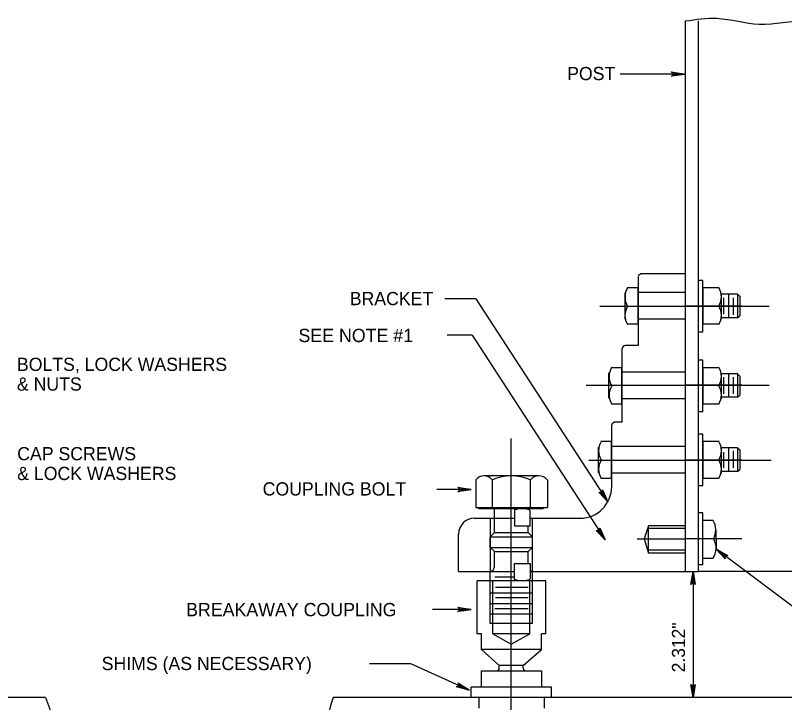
# Model space of a CAD drawing. Extents: x 637580 to 641008, y 294594 to 295782.
# Drawn here: x 637787.5 to 637964.6, y 294775.2 to 294933.4 of the extents above; entities that cross this region are included whole.
import ezdxf

# ---------------------------------------------------------------- set-up
doc = ezdxf.new("R2010")
doc.units = 0
for name, color, linetype in [('1', 7, 'Continuous'), ('2', 7, 'Continuous'), ('3', 7, 'Continuous')]:
    doc.layers.add(name, color=color, linetype=linetype)

# ---------------------------------------------------------------- blocks, each defined once
blk = doc.blocks.new('RARROW')
at = {"layer": '3'}
blk.add_lwpolyline([(-2.2695, 0.285), (-2.184875, 0.12075), (0, 0), (-2.2695, 0.285), (-2.38575, 0.384625), (0, 0), (-2.183125, -0.108), (-2.262875, -0.2705), (0, 0), (-2.38575, -0.379125), (-2.262875, -0.2705)], dxfattribs=at)

msp = doc.modelspace()

# ---------------------------------------------------------------- linework, layer by layer
at = {"layer": '2'}
for p, q in [((637941.8, 294866.5), (637941.8, 294932.13)), ((637944.8, 294805.38), (637944.8, 294932.13)), ((637941.55, 294919.88), (637926.8, 294919.88)), ((637941.8, 294873.88), (637931.43, 294873.88)), ((637930.93, 294873.13), (637930.93, 294857.38)), ((637945.8, 294872.38), (637944.93, 294872.38)), ((637945.8, 294860.5), (637945.8, 294872.38)), ((637928.43, 294870.75), (637930.93, 294870.75)), ((637930.93, 294862.38), (637930.93, 294870.75)), ((637930.93, 294862.38), (637930.93, 294870.75)), ((637945.8, 294870.75), (637945.8, 294862.38)), ((637945.8, 294870.75), (637949.55, 294870.75)), ((637927.93, 294866.5), (637927.93, 294869.5)), ((637941.8, 294869.63), (637930.93, 294869.63)), ((637950.05, 294869.25), (637950.05, 294866.5)), ((637953.8, 294869.25), (637950.05, 294869.25)), ((637950.55, 294868.38), (637950.55, 294864.63)), ((637951.68, 294869.25), (637951.68, 294863.75)), ((637952.8, 294868.38), (637952.8, 294864.5)), ((637953.8, 294869.25), (637953.8, 294863.75)), ((637953.8, 294869.25), (637954.3, 294868.75)), ((637954.3, 294868.75), (637954.3, 294864.25)), ((637893.55, 294868.13), (637886.39, 294868.13)), ((637893.55, 294868.13), (637923.93, 294821.38)), ((637922.05, 294866.5), (637961.05, 294866.5)), ((637927.93, 294866.5), (637930.93, 294866.5)), ((637927.93, 294866.5), (637927.93, 294866.5)), ((637927.93, 294863.5), (637927.93, 294866.5)), ((637930.93, 294866.5), (637930.93, 294866.5)), ((637930.93, 294866.5), (637930.93, 294866.5)), ((637930.93, 294866.5), (637930.93, 294866.5)), ((637930.93, 294866.5), (637930.93, 294866.5)), ((637930.93, 294866.5), (637930.93, 294866.5)), ((637941.8, 294848.25), (637941.8, 294866.5)), ((637954.8, 294866.5), (637941.8, 294866.5)), ((637945.8, 294866.5), (637945.8, 294866.5)), ((637945.8, 294866.5), (637950.05, 294866.5)), ((637945.8, 294866.5), (637945.8, 294866.5)), ((637950.05, 294866.5), (637950.05, 294866.5)), ((637950.05, 294866.5), (637950.05, 294863.5)), ((637950.05, 294866.5), (637950.05, 294866.5)), ((637941.8, 294863.5), (637930.93, 294863.5)), ((637953.8, 294863.75), (637950.05, 294863.75)), ((637953.8, 294863.75), (637954.3, 294864.25)), ((637928.43, 294862.38), (637930.93, 294862.38)), ((637945.8, 294862.38), (637949.43, 294862.38)), ((637892.68, 294859.75), (637886.95, 294859.75)), ((637892.68, 294859.75), (637923.3, 294812.63)), ((637945.8, 294860.5), (637944.68, 294860.5)), ((637927.18, 294856.75), (637927.18, 294839.75)), ((637930.93, 294857.38), (637927.93, 294857.38)), ((637924.8, 294852.38), (637927.18, 294852.38)), ((637927.18, 294844), (637927.18, 294852.38)), ((637927.18, 294844), (637927.18, 294852.38)), ((637927.18, 294844), (637927.18, 294852.38)), ((637945.8, 294854), (637944.93, 294854)), ((637945.8, 294842.13), (637945.8, 294854)), ((637945.8, 294852.38), (637945.8, 294844)), ((637945.8, 294852.38), (637949.55, 294852.38)), ((637924.18, 294848.25), (637924.18, 294851.13)), ((637941.8, 294851.25), (637927.18, 294851.25)), ((637950.05, 294851), (637950.05, 294848.25)), ((637953.8, 294850.88), (637950.05, 294850.88)), ((637951.68, 294850.88), (637951.68, 294845.5)), ((637953.8, 294850.88), (637953.8, 294845.5)), ((637953.8, 294850.88), (637954.3, 294850.38)), ((637950.55, 294850.13), (637950.55, 294846.25)), ((637952.8, 294850.13), (637952.8, 294846.25)), ((637954.3, 294850.38), (637954.3, 294846)), ((637918.93, 294848.25), (637961.05, 294848.25)), ((637924.18, 294848.25), (637927.18, 294848.25)), ((637924.18, 294848.25), (637924.18, 294848.25)), ((637924.18, 294845.25), (637924.18, 294848.13)), ((637927.18, 294848.25), (637927.18, 294848.25)), ((637927.18, 294848.25), (637927.18, 294848.25)), ((637927.18, 294848.25), (637927.18, 294848.25)), ((637927.18, 294848.25), (637927.18, 294848.25)), ((637927.18, 294848.25), (637927.18, 294848.25)), ((637927.18, 294848.25), (637927.18, 294848.25)), ((637927.18, 294848.25), (637927.18, 294848.25)), ((637927.18, 294848.25), (637927.18, 294848.25)), ((637941.8, 294831), (637941.8, 294848.25)), ((637954.8, 294848.25), (637941.8, 294848.25)), ((637945.8, 294848.25), (637945.8, 294848.25)), ((637945.8, 294848.25), (637945.8, 294848.25)), ((637945.8, 294848.25), (637950.05, 294848.25)), ((637945.8, 294848.25), (637945.8, 294848.25)), ((637950.05, 294848.25), (637950.05, 294848.25)), ((637950.05, 294848.25), (637950.05, 294845.13)), ((637950.05, 294848.25), (637950.05, 294848.25)), ((637953.8, 294845.5), (637950.05, 294845.5)), ((637953.8, 294845.5), (637954.3, 294846)), ((637924.8, 294844), (637927.18, 294844)), ((637941.8, 294845.13), (637927.18, 294845.13)), ((637945.8, 294844), (637949.43, 294844)), ((637945.8, 294842.13), (637944.8, 294842.13)), ((637924.8, 294839.13), (637924.8, 294825)), ((637927.18, 294839.75), (637925.3, 294839.75)), ((637945.8, 294837), (637944.93, 294837)), ((637945.8, 294825.13), (637945.8, 294837)), ((637901.68, 294768.25), (637901.68, 294836)), ((637922.3, 294835.38), (637924.8, 294835.38)), ((637924.8, 294826.88), (637924.8, 294835.38)), ((637924.8, 294826.88), (637924.8, 294835.38)), ((637924.8, 294826.88), (637924.8, 294835.38)), ((637924.8, 294826.88), (637924.8, 294835.38)), ((637945.8, 294835.38), (637945.8, 294826.88)), ((637945.8, 294835.38), (637949.55, 294835.38)), ((637921.8, 294831.13), (637921.8, 294834)), ((637941.8, 294834.13), (637924.8, 294834.13)), ((637950.05, 294833.88), (637950.05, 294831.13)), ((637953.8, 294833.88), (637950.05, 294833.88)), ((637950.55, 294832.88), (637950.55, 294829.25)), ((637951.68, 294833.88), (637951.68, 294828.38)), ((637952.8, 294833.13), (637952.8, 294829.25)), ((637953.8, 294833.88), (637953.8, 294828.38)), ((637953.8, 294833.88), (637954.3, 294833.38)), ((637954.3, 294833.38), (637954.3, 294828.88)), ((637950.05, 294831.13), (637950.05, 294828)), ((637919.55, 294831), (637961.55, 294831)), ((637921.8, 294831), (637924.8, 294831)), ((637921.8, 294831), (637921.8, 294831)), ((637921.8, 294828.13), (637921.8, 294831)), ((637924.8, 294831), (637924.8, 294831)), ((637924.8, 294831), (637924.8, 294831)), ((637924.8, 294831), (637924.8, 294831)), ((637924.8, 294831), (637924.8, 294831)), ((637924.8, 294831), (637924.8, 294831)), ((637924.8, 294831), (637924.8, 294831)), ((637924.8, 294831), (637924.8, 294831)), ((637924.8, 294831), (637924.8, 294831)), ((637924.8, 294831), (637924.8, 294831)), ((637924.8, 294831), (637924.8, 294831)), ((637941.8, 294812.88), (637941.8, 294831)), ((637954.8, 294831), (637941.8, 294831)), ((637945.8, 294831), (637945.8, 294831)), ((637945.8, 294831), (637945.8, 294831)), ((637945.8, 294831), (637945.8, 294831)), ((637945.8, 294831), (637950.05, 294831)), ((637945.8, 294831), (637945.8, 294831)), ((637950.05, 294831), (637950.05, 294831)), ((637950.05, 294831), (637950.05, 294831)), ((637941.8, 294828), (637924.8, 294828)), ((637953.8, 294828.38), (637950.05, 294828.38)), ((637953.8, 294828.38), (637954.3, 294828.88)), ((637893.55, 294826.5), (637893.55, 294826.5)), ((637893.55, 294826.5), (637893.55, 294820.13)), ((637895.43, 294827.5), (637895.43, 294827.5)), ((637895.43, 294827.5), (637897.3, 294827.5)), ((637897.3, 294827.5), (637906.05, 294827.5)), ((637897.3, 294826.5), (637897.3, 294820.13)), ((637897.3, 294826.5), (637897.3, 294826.5)), ((637901.68, 294827.5), (637901.68, 294827.5)), ((637901.68, 294793.88), (637901.68, 294827.38)), ((637906.05, 294827.5), (637907.93, 294827.5)), ((637906.05, 294826.5), (637906.05, 294820.25)), ((637906.05, 294826.5), (637906.05, 294826.5)), ((637907.93, 294827.5), (637907.93, 294827.5)), ((637910.05, 294826.5), (637910.05, 294826.5)), ((637910.05, 294826.5), (637910.05, 294820.13)), ((637922.3, 294826.88), (637924.8, 294826.88)), ((637945.8, 294826.88), (637949.43, 294826.88)), ((637892.42, 294824.25), (637884.57, 294824.25)), ((637945.8, 294825.13), (637944.8, 294825.13)), ((637893.55, 294820.13), (637910.05, 294820.13)), ((637894.18, 294819.88), (637894.05, 294820.13)), ((637894.18, 294819.88), (637909.05, 294819.88)), ((637897.8, 294814.38), (637897.8, 294820.13)), ((637901.68, 294819.88), (637901.68, 294819.88)), ((637901.68, 294819.88), (637901.68, 294819.88)), ((637902.43, 294819.5), (637902.43, 294815.88)), ((637904.18, 294819.88), (637904.18, 294819.88)), ((637906.05, 294815.88), (637906.05, 294819.5)), ((637909.05, 294819.88), (637909.18, 294820.25)), ((637945.8, 294818.88), (637944.8, 294818.88)), ((637945.8, 294806.88), (637945.8, 294818.88)), ((637893.18, 294817.63), (637902.3, 294817.63)), ((637896.8, 294817.63), (637896.8, 294805.38)), ((637906.05, 294817.63), (637917.55, 294817.63)), ((637906.55, 294805.38), (637906.55, 294817.63)), ((637945.8, 294808.38), (637945.8, 294817.13)), ((637945.8, 294808.38), (637945.8, 294817.13)), ((637948.18, 294817.13), (637945.8, 294817.13)), ((637902.43, 294815.88), (637906.05, 294815.88)), ((637904.18, 294815.88), (637904.18, 294815.88)), ((637905.55, 294814.38), (637905.55, 294815.88)), ((637933.3, 294815.88), (637932.3, 294812.88)), ((637941.8, 294815.88), (637933.3, 294815.88)), ((637933.3, 294809.63), (637933.3, 294815.88)), ((637941.8, 294815.25), (637933.3, 294815.25)), ((637889.55, 294805.38), (637889.55, 294814)), ((637896.8, 294813.38), (637897.8, 294814.38)), ((637896.8, 294813.38), (637906.55, 294813.38)), ((637896.8, 294810.88), (637896.8, 294813.38)), ((637897.8, 294814.38), (637905.55, 294814.38)), ((637906.55, 294813.38), (637905.55, 294814.38)), ((637906.55, 294810.88), (637906.55, 294813.38)), ((637948.78, 294814.93), (637948.88, 294810.69)), ((637930.68, 294812.88), (637941.8, 294812.88)), ((637932.3, 294812.88), (637933.3, 294809.63)), ((637941.8, 294805.38), (637941.8, 294812.88)), ((637954.8, 294812.88), (637941.8, 294812.88)), ((637945.8, 294812.88), (637945.8, 294812.88)), ((637945.8, 294812.88), (637945.8, 294812.88)), ((637945.8, 294812.88), (637945.8, 294812.88)), ((637945.8, 294812.88), (637945.8, 294812.88)), ((637945.8, 294812.88), (637945.8, 294812.88)), ((637948.93, 294812.88), (637945.8, 294812.88)), ((637945.8, 294812.88), (637945.8, 294812.88)), ((637896.8, 294810.88), (637906.55, 294810.88)), ((637897.8, 294810), (637896.8, 294810.88)), ((637897.8, 294806.38), (637897.8, 294810)), ((637897.8, 294810), (637905.55, 294810)), ((637901.68, 294810.63), (637901.68, 294810.63)), ((637901.68, 294810.63), (637901.68, 294810.63)), ((637905.55, 294810), (637906.55, 294810.88)), ((637905.55, 294807.25), (637905.55, 294810)), ((637941.8, 294810.25), (637933.3, 294810.25)), ((637969.48, 294795.04), (637948.86, 294810.49)), ((637941.8, 294809.63), (637933.3, 294809.63)), ((637948.09, 294808.38), (637945.8, 294808.38)), ((637902.43, 294807.25), (637906.05, 294807.25)), ((637902.43, 294803.63), (637902.43, 294807.25)), ((637904.18, 294807.25), (637904.18, 294807.25)), ((637906.05, 294807.25), (637906.05, 294803.63)), ((637945.8, 294806.88), (637944.93, 294806.88)), ((637889.55, 294805.38), (637889.55, 294805.38)), ((637889.55, 294805.38), (637902.43, 294805.38)), ((637896.8, 294795.63), (637896.8, 294805.38)), ((637901.68, 294805.38), (637901.68, 294805.38)), ((637901.68, 294805.38), (637901.68, 294805.38)), ((637906.05, 294805.38), (637944.8, 294805.38)), ((637906.55, 294795.63), (637906.55, 294805.38)), ((637943.55, 294805.38), (637943.55, 294776.38)), ((638075.05, 294805.38), (637944.8, 294805.38)), ((637893.8, 294791), (637893.8, 294803.25)), ((637909.68, 294803.25), (637893.8, 294803.25)), ((637896.8, 294793.38), (637896.8, 294803.25)), ((637897.43, 294791), (637897.43, 294803.25)), ((637897.93, 294804.13), (637902.3, 294804.13)), ((637901.68, 294803.25), (637901.68, 294803.25)), ((637901.68, 294803.25), (637901.68, 294803.25)), ((637904.18, 294803.25), (637904.18, 294803.25)), ((637905.93, 294791), (637905.93, 294803.25)), ((637906.55, 294793.38), (637906.55, 294803.25)), ((637909.68, 294791), (637909.68, 294803.25)), ((637898.05, 294801.75), (637905.55, 294801.75)), ((637896.8, 294800.5), (637906.55, 294800.5)), ((637898.05, 294799.38), (637905.55, 294799.38)), ((637896.8, 294798), (637906.55, 294798)), ((637892.42, 294796.63), (637883.56, 294796.63)), ((637897.93, 294796.88), (637905.55, 294796.88)), ((637896.8, 294795.63), (637906.55, 294795.63)), ((637901.68, 294795.63), (637901.68, 294795.63)), ((637906.55, 294793.38), (637896.8, 294793.38)), ((637894.8, 294791), (637893.8, 294791)), ((637894.8, 294787.38), (637894.8, 294791)), ((637905.93, 294791), (637897.43, 294791)), ((637897.43, 294791), (637901.68, 294788.63)), ((637901.68, 294788.63), (637905.93, 294791)), ((637908.68, 294787.38), (637908.68, 294791)), ((637909.68, 294791), (637908.68, 294791)), ((637901.68, 294788.63), (637901.68, 294788.63)), ((637898.93, 294783.75), (637894.8, 294787.38)), ((637908.68, 294787.38), (637894.8, 294787.38)), ((637904.43, 294783.75), (637908.68, 294787.38)), ((637878.55, 294784.13), (637869.06, 294784.13)), ((637892, 294778.06), (637878.55, 294784.13)), ((637904.43, 294783.75), (637898.93, 294783.75)), ((637898.93, 294783.1), (637898.93, 294783.75)), ((637904.43, 294783.1), (637904.43, 294783.75)), ((637894.8, 294782.5), (637908.68, 294782.5)), ((637894.8, 294778.75), (637894.8, 294782.5)), ((637908.68, 294782.5), (637908.68, 294778.75)), ((637910.93, 294778.75), (637892.43, 294778.75)), ((637892.43, 294776.38), (637892.43, 294778.75)), ((637901.68, 294778.75), (637901.68, 294778.75)), ((637910.93, 294776.38), (637910.93, 294778.75)), ((637794.44, 294776.38), (637673.31, 294776.38)), ((638166.68, 294776.38), (637860.68, 294776.38)), ((637910.93, 294776.38), (637892.43, 294776.38)), ((637894.18, 294776.38), (637894.18, 294773.88)), ((637909.3, 294773.88), (637909.3, 294776.38))]:
    msp.add_line(p, q, dxfattribs=at)
for centre, start, end in [((637898.33, 294783.1), 270, 0), ((637905.03, 294783.1), 180, 270)]:
    msp.add_arc(centre, 0.6, start, end, dxfattribs=at)
for centre, major_axis, start_param, end_param in [((637931.52, 294873.21), (0, -0.61), 3.141593, 4.712389), ((637932.04, 294868.59), (0, -4.18), 4.16723, 5.257548), ((637946.02, 294868.62), (0, 4.08), 4.160577, 5.264201), ((637931.77, 294864.33), (0, -3.91), 4.129616, 5.27673), ((637946.14, 294864.34), (0, 3.96), 4.15179, 5.282205), ((637927.86, 294856.74), (0, -0.61), 3.141593, 4.712389), ((637928.38, 294850.26), (0, -4.18), 4.16723, 5.257548), ((637946.02, 294850.29), (0, 4.08), 4.160577, 5.264201), ((637928.11, 294846), (0, -3.91), 4.129616, 5.27673), ((637946.14, 294846.02), (0, 3.96), 4.15179, 5.282205), ((637925.43, 294839.04), (0, -0.61), 3.141593, 4.712389), ((637925.95, 294833.17), (0, -4.18), 4.16723, 5.257548), ((637946.02, 294833.2), (0, 4.08), 4.160577, 5.264201), ((637925.68, 294828.91), (0, -3.91), 4.129616, 5.27673), ((637946.14, 294828.92), (0, 3.96), 4.15179, 5.282205), ((637901.69, 294816.68), (0, -10.74), 2.718335, 3.56485), ((637895.4, 294825.03), (0, -2.39), 2.218404, 4.064781), ((637908.01, 294824.98), (0, -2.44), 2.228521, 4.054665), ((637917.52, 294824.96), (0, -7.33), 0, 1.570796), ((637904.16, 294814.07), (0, -5.72), 2.814747, 3.468439), ((637893.22, 294813.97), (0, -3.67), 3.141593, 4.712389), ((637944.61, 294814.96), (0, 4.18), 4.19139, 5.257548), ((637944.98, 294810.73), (0, 3.91), 4.066903, 5.295162), ((637896.85, 294806.35), (0, 0.914), 3.141593, 4.712389), ((637906.58, 294806.35), (0, -0.914), 5.587635, 6.283185), ((637904.16, 294809), (0, -5.72), 5.956339, 6.610031)]:
    msp.add_ellipse(centre, major_axis=major_axis, ratio=0.996388, start_param=start_param, end_param=end_param, dxfattribs=at)
for points in [[(637941.8, 294932.13), (637949.05, 294932.75), (637958.8, 294931.38), (637969.68, 294932.25), (637980.43, 294931.38), (637990.18, 294932.25), (637999.3, 294929.75), (638009.05, 294931.75), (638018.3, 294930.25), (638028.55, 294932.75), (638039.8, 294931.75)], [(637794.44, 294776.38), (637796.31, 294766.5), (637793.69, 294758.5), (637794.44, 294746.88), (637792.69, 294737), (637795.31, 294727.63), (637793.19, 294719.13), (637795.81, 294709.38), (637793.69, 294703.13), (637794.06, 294697.25)], [(637860.68, 294776.38), (637859.3, 294768.88), (637861.55, 294760.38), (637858.93, 294748.38), (637862.05, 294737.13), (637858.93, 294727.63), (637862.05, 294718.75), (637858.43, 294709), (637860.68, 294702.13), (637860.68, 294698.13)]]:
    msp.add_spline(points, degree=3, dxfattribs=at)

# ---------------------------------------------------------------- block references
at = {"layer": '2', "xscale": 1.2574347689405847, "yscale": 1.3092961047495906}
for p in [(637941.55, 294919.88), (637892.42, 294824.25), (637892.42, 294796.63)]:
    msp.add_blockref('RARROW', p, dxfattribs=at)
at = {"layer": '2'}
for p, xscale, yscale, rotation in [((637923.92, 294821.38), 1.2574347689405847, 1.3092961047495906, -57.059664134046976), ((637923.3, 294812.63), 1.2574347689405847, 1.3092961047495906, -56.36233542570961), ((637948.86, 294810.49), 1.2574347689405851, 1.3092961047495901, 143.29217381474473), ((637943.55, 294805.38), 1.2574347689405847, 1.3092961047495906, 89.99999999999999), ((637892, 294778.06), 1.2574347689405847, 1.3092961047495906, -24.173035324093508), ((637943.55, 294776.38), 1.2574347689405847, 1.3092961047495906, -90.00000000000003)]:
    msp.add_blockref('RARROW', p, dxfattribs=dict(at, xscale=xscale, yscale=yscale, rotation=rotation))

# ---------------------------------------------------------------- texts
at = {"layer": '1'}
for s, height, p in [('CAP SCREWS', 3.044, (637787.92, 294830.98)), ('& LOCK WASHERS', 3.0442, (637787.92, 294826.43))]:
    msp.add_text(s, height=height, dxfattribs=at).set_placement(p)
msp.add_text('2.312"', height=3, rotation=90, dxfattribs=at).set_placement((637941.68, 294782.17))
at = {"layer": '3'}
for s, height, p in [('POST', 3.043, (637914.55, 294918.5)), ('BRACKET', 3.043, (637864.5, 294866.69)), ('SEE NOTE #1', 3.0608, (637852.69, 294858.19)), ('BOLTS, LOCK WASHERS', 3.0427, (637787.86, 294851.55)), ('& NUTS', 3.043, (637787.86, 294847.01)), ('COUPLING BOLT', 3.0442, (637844.44, 294822.87)), ('BREAKAWAY COUPLING', 3.0608, (637826.81, 294795.07)), ('SHIMS (AS NECESSARY)', 3.0427, (637807.38, 294782.67))]:
    msp.add_text(s, height=height, dxfattribs=at).set_placement(p)

doc.saveas('drawing.dxf')
